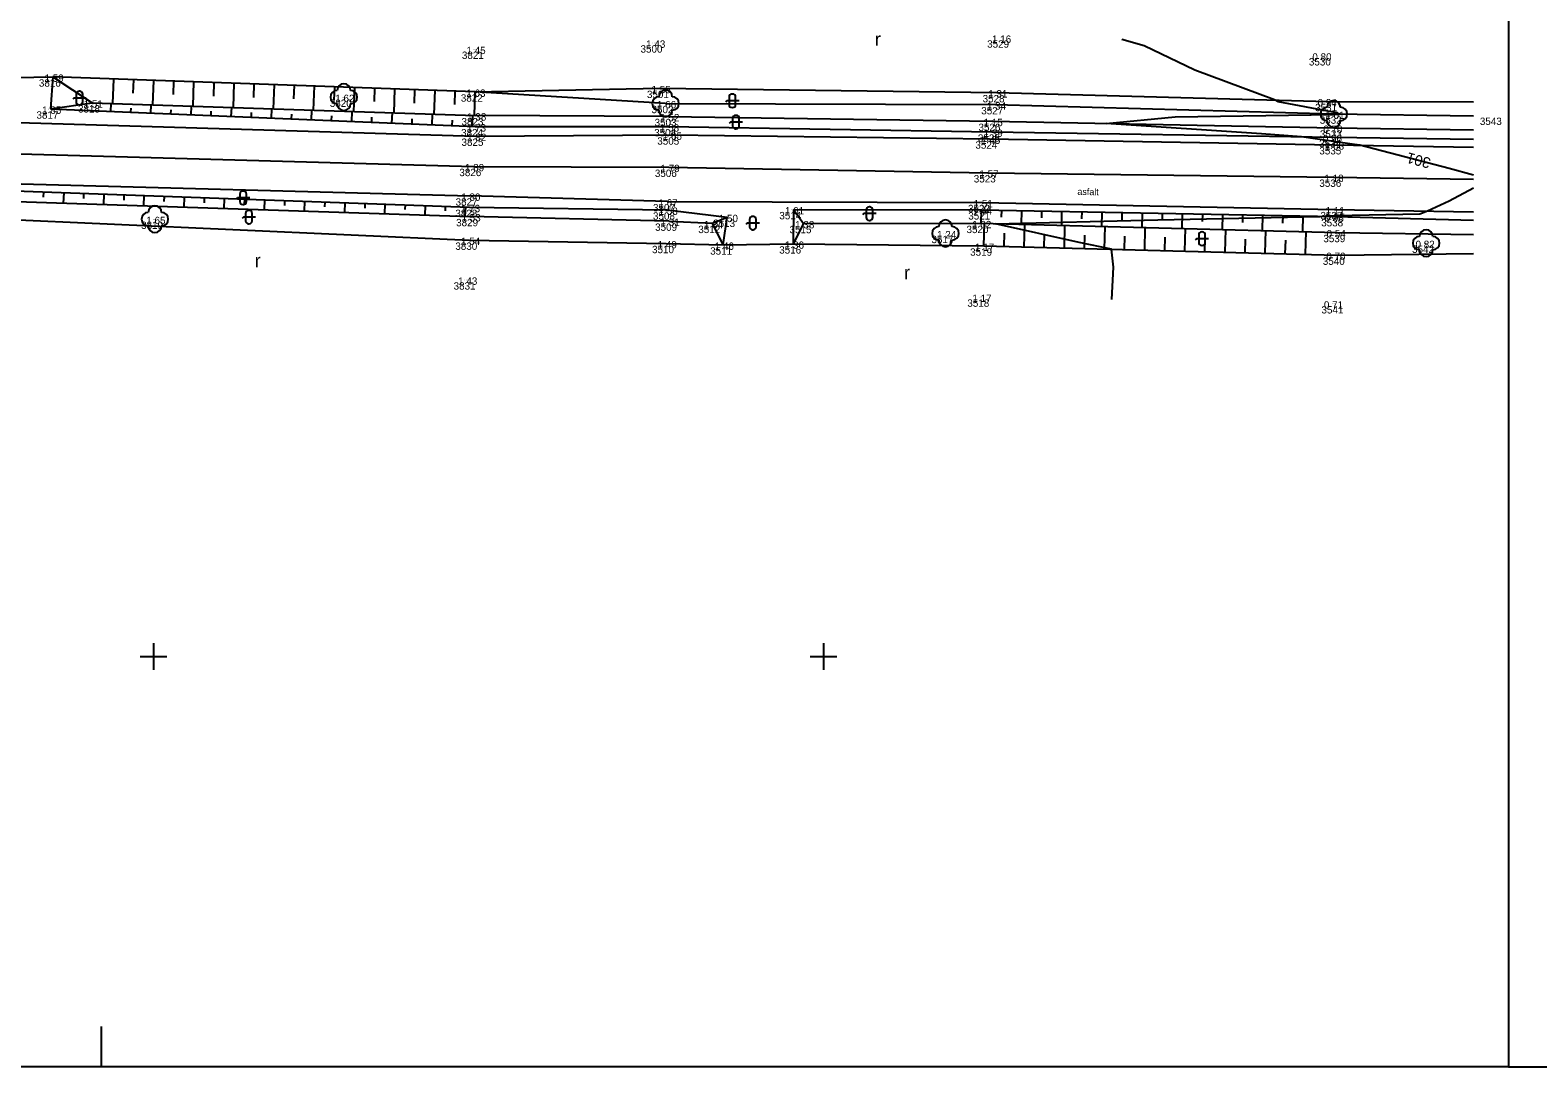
# Model space of a CAD drawing. Extents: x -740053 to -737517, y -1033516 to -1032476.
# Drawn here: x -739209.2 to -739096.7, y -1032630.6 to -1032553.3 of the extents above; entities that cross this region are included whole.
import ezdxf

# ---------------------------------------------------------------- set-up
doc = ezdxf.new("R2010")
doc.units = 0
for name, color, linetype in [('bod-cislo', 7, 'Continuous'), ('bod-oznac', 7, 'Continuous'), ('bod-vyska', 7, 'Continuous'), ('bod-vyska100', 7, 'Continuous'), ('Contours', 7, 'Continuous'), ('Contours text', 7, 'Continuous'), ('ctv-sit', 7, 'Continuous'), ('nazvy-bud-povr', 7, 'Continuous'), ('osa-komunikace', 7, 'Continuous'), ('Predmety bez rozlišeni', 7, 'Continuous'), ('promika-formát', 7, 'Continuous'), ('rozhraní kultůr', 7, 'Continuous'), ('silnice', 7, 'Continuous'), ('Technické šrafy', 7, 'Continuous'), ('Terenni-hrana', 7, 'Continuous'), ('Znacky-kultury', 7, 'Continuous')]:
    doc.layers.add(name, color=color, linetype=linetype)

# ---------------------------------------------------------------- blocks, each defined once
blk = doc.blocks.new('POINT_DISPLAY')
blk.add_line((0, 0), (0, 0))
blk = doc.blocks.new('p_strom')
for centre, start, end in [((-1, 0), 90, 270), ((0, 1), 0, 180), ((1, 0), 270, 90), ((0, -1), 180, 0)]:
    blk.add_arc(centre, 1, start, end)
at = {"rotation": -180}
blk.add_blockref('POINT_DISPLAY', (0, 0), dxfattribs=at)
blk = doc.blocks.new('p_neplod')
for p, q in [((-0.82, 0), (-0.99, -0.18)), ((1, 0), (-0.82, 0)), ((-0.49, 0.56), (-0.49, -0.55)), ((0.05, 1.01), (-0.04, 1.01)), ((0.5, -0.55), (0.5, 0.56)), ((-0.04, -1), (0.05, -1))]:
    blk.add_line(p, q)
for centre, start, end in [((-0.04, 0.56), 90, 180), ((0.05, 0.56), 0, 90), ((-0.04, -0.55), 180, 270), ((0.05, -0.55), 270, 0)]:
    blk.add_arc(centre, 0.45, start, end)
blk = doc.blocks.new('p_orna')
blk.add_text('r', height=2).set_placement((0, 0))
blk = doc.blocks.new('ctvsit')
for p, q in [((2, 0), (-2, 0)), ((0, -2), (0, 2))]:
    blk.add_line(p, q)

msp = doc.modelspace()

# ---------------------------------------------------------------- linework, layer by layer
at = {"layer": 'Contours'}
for points in [[(-739101.49, -1032564.07), (-739103.31, -1032563.58), (-739109.97, -1032561.84), (-739110.37, -1032561.79), (-739111.95, -1032561.56), (-739114.32, -1032561.21), (-739117.31, -1032561), (-739128.9, -1032560.22), (-739123.76, -1032559.73), (-739111.92, -1032559.54), (-739111.57, -1032559.53), (-739111.44, -1032559.52), (-739111.55, -1032559.51), (-739111.98, -1032559.38), (-739116.07, -1032558.61), (-739116.35, -1032558.46), (-739122.28, -1032556.24), (-739126.08, -1032554.42), (-739127.74, -1032553.96)], [(-739128.48, -1032573.35), (-739128.36, -1032570.95), (-739128.5, -1032569.61), (-739130.92, -1032569.09), (-739137.17, -1032567.7), (-739125.05, -1032567.42), (-739112.96, -1032567.15), (-739111.82, -1032567.09), (-739105.49, -1032566.96), (-739104.94, -1032566.75), (-739103.32, -1032565.98), (-739101.49, -1032565.01)]]:
    msp.add_lwpolyline(points, dxfattribs=at)
at = {"layer": 'osa-komunikace'}
for p, q in [((-739213.83, -1032562.39), (-739176.13, -1032563.42)), ((-739176.13, -1032563.42), (-739161.54, -1032563.48)), ((-739161.54, -1032563.48), (-739137.74, -1032563.89)), ((-739137.74, -1032563.89), (-739111.95, -1032564.22)), ((-739111.95, -1032564.22), (-739101.49, -1032564.37))]:
    msp.add_line(p, q, dxfattribs=at)
at = {"layer": 'Predmety bez rozlišeni'}
for p, q in [((-739203.88, -1032630.63), (-739203.88, -1032627.63)), ((-739203.88, -1032630.63), (-739308.88, -1032630.63)), ((-739098.88, -1032630.63), (-739203.88, -1032630.63))]:
    msp.add_line(p, q, dxfattribs=at)
at = {"layer": 'promika-formát'}
msp.add_lwpolyline([(-739098.88, -1032630.63), (-738993.88, -1032630.63), (-738993.88, -1032482.13), (-739098.88, -1032482.13)], close=True, dxfattribs=at)
at = {"layer": 'rozhraní kultůr'}
for p, q in [((-739213.24, -1032556.83), (-739207.51, -1032556.74)), ((-739176.02, -1032557.86), (-739162.21, -1032557.59)), ((-739162.21, -1032557.59), (-739137.08, -1032557.91)), ((-739137.08, -1032557.91), (-739112.34, -1032558.57)), ((-739112.34, -1032558.57), (-739101.49, -1032558.6)), ((-739214.13, -1032567.24), (-739176.43, -1032568.92)), ((-739176.43, -1032568.92), (-739161.75, -1032569.17)), ((-739161.75, -1032569.17), (-739157.49, -1032569.28))]:
    msp.add_line(p, q, dxfattribs=at)
at = {"layer": 'silnice'}
for p, q in [((-739213.3, -1032560.06), (-739175.97, -1032561.16)), ((-739175.97, -1032561.16), (-739161.36, -1032561.07)), ((-739161.36, -1032561.07), (-739137.61, -1032561.37)), ((-739137.61, -1032561.37), (-739111.95, -1032561.8)), ((-739111.95, -1032561.8), (-739101.49, -1032561.99)), ((-739213.9, -1032564.62), (-739176.41, -1032565.62)), ((-739161.68, -1032566.05), (-739176.41, -1032565.62)), ((-739161.68, -1032566.05), (-739138.17, -1032566.11)), ((-739138.17, -1032566.11), (-739111.87, -1032566.64)), ((-739111.87, -1032566.64), (-739101.49, -1032566.81))]:
    msp.add_line(p, q, dxfattribs=at)
at = {"layer": 'Technické šrafy'}
for p, q in [((-739203, -1032556.9), (-739203.07, -1032558.72)), ((-739201.5, -1032556.95), (-739201.54, -1032557.95)), ((-739200, -1032557.01), (-739200.07, -1032558.82)), ((-739198.51, -1032557.06), (-739198.54, -1032558.06)), ((-739197.01, -1032557.11), (-739197.07, -1032558.92)), ((-739195.51, -1032557.17), (-739195.54, -1032558.17)), ((-739194.01, -1032557.22), (-739194.07, -1032559.02)), ((-739192.51, -1032557.27), (-739192.55, -1032558.27)), ((-739191.01, -1032557.33), (-739191.07, -1032559.12)), ((-739189.51, -1032557.38), (-739189.55, -1032558.38)), ((-739188.01, -1032557.43), (-739188.08, -1032559.22)), ((-739186.51, -1032557.49), (-739186.55, -1032558.49)), ((-739185.01, -1032557.54), (-739185.08, -1032559.32)), ((-739183.52, -1032557.59), (-739183.55, -1032558.59)), ((-739182.02, -1032557.65), (-739182.08, -1032559.43)), ((-739180.52, -1032557.7), (-739180.55, -1032558.7)), ((-739179.02, -1032557.75), (-739179.08, -1032559.53)), ((-739177.52, -1032557.81), (-739177.55, -1032558.81)), ((-739176.02, -1032557.86), (-739176.08, -1032559.63)), ((-739203.19, -1032559.32), (-739203.17, -1032558.72)), ((-739201.7, -1032559.38), (-739201.68, -1032559.07)), ((-739200.2, -1032559.44), (-739200.17, -1032558.82)), ((-739197.2, -1032559.57), (-739197.17, -1032558.92)), ((-739194.2, -1032559.69), (-739194.17, -1032559.02)), ((-739198.7, -1032559.5), (-739198.68, -1032559.19)), ((-739195.7, -1032559.63), (-739195.69, -1032559.3)), ((-739192.7, -1032559.75), (-739192.69, -1032559.41)), ((-739191.2, -1032559.82), (-739191.18, -1032559.12)), ((-739189.71, -1032559.88), (-739189.69, -1032559.52)), ((-739188.21, -1032559.94), (-739188.18, -1032559.22)), ((-739186.71, -1032560), (-739186.69, -1032559.64)), ((-739185.21, -1032560.07), (-739185.18, -1032559.32)), ((-739183.71, -1032560.13), (-739183.7, -1032559.75)), ((-739182.21, -1032560.19), (-739182.18, -1032559.42)), ((-739180.71, -1032560.25), (-739180.7, -1032559.86)), ((-739179.21, -1032560.32), (-739179.18, -1032559.52)), ((-739177.72, -1032560.38), (-739177.7, -1032559.98)), ((-739176.22, -1032560.44), (-739176.18, -1032559.62)), ((-739208.21, -1032565.33), (-739208.23, -1032565.72)), ((-739206.71, -1032565.39), (-739206.74, -1032566.16)), ((-739205.22, -1032565.44), (-739205.23, -1032565.83)), ((-739203.72, -1032565.49), (-739203.74, -1032566.26)), ((-739202.22, -1032565.55), (-739202.23, -1032565.93)), ((-739200.72, -1032565.6), (-739200.75, -1032566.36)), ((-739199.22, -1032565.66), (-739199.23, -1032566.03)), ((-739197.72, -1032565.71), (-739197.75, -1032566.46)), ((-739196.22, -1032565.76), (-739196.23, -1032566.13)), ((-739194.72, -1032565.82), (-739194.75, -1032566.56)), ((-739193.22, -1032565.87), (-739193.24, -1032566.24)), ((-739191.72, -1032565.92), (-739191.75, -1032566.65)), ((-739190.23, -1032565.98), (-739190.24, -1032566.34)), ((-739188.73, -1032566.03), (-739188.75, -1032566.75)), ((-739187.23, -1032566.08), (-739187.24, -1032566.44)), ((-739185.73, -1032566.14), (-739185.75, -1032566.85)), ((-739184.23, -1032566.19), (-739184.24, -1032566.55)), ((-739182.73, -1032566.24), (-739182.76, -1032566.95)), ((-739181.23, -1032566.3), (-739181.24, -1032566.65)), ((-739179.73, -1032566.35), (-739179.76, -1032567.05)), ((-739178.23, -1032566.41), (-739178.25, -1032566.75)), ((-739176.73, -1032566.46), (-739176.76, -1032567.15)), ((-739138.23, -1032566.66), (-739138.25, -1032567.67)), ((-739136.73, -1032566.69), (-739136.74, -1032567.2)), ((-739135.23, -1032566.72), (-739135.25, -1032567.75)), ((-739133.73, -1032566.75), (-739133.74, -1032567.27)), ((-739132.23, -1032566.78), (-739132.25, -1032567.82)), ((-739130.73, -1032566.8), (-739130.74, -1032567.33)), ((-739129.23, -1032566.83), (-739129.25, -1032567.9)), ((-739127.73, -1032566.86), (-739127.74, -1032567.4)), ((-739126.23, -1032566.89), (-739126.25, -1032567.98)), ((-739124.73, -1032566.92), (-739124.74, -1032567.47)), ((-739123.23, -1032566.95), (-739123.25, -1032568.05)), ((-739138.03, -1032569.36), (-739137.99, -1032567.68)), ((-739135.03, -1032569.44), (-739134.99, -1032567.75)), ((-739132.03, -1032569.51), (-739131.99, -1032567.83)), ((-739129.03, -1032569.59), (-739128.99, -1032567.91)), ((-739126.03, -1032569.67), (-739125.99, -1032567.98)), ((-739123.03, -1032569.75), (-739122.99, -1032568.06)), ((-739121.73, -1032566.98), (-739121.74, -1032567.54)), ((-739120.23, -1032567.01), (-739120.26, -1032568.13)), ((-739118.73, -1032567.04), (-739118.74, -1032567.6)), ((-739117.23, -1032567.07), (-739117.26, -1032568.21)), ((-739115.73, -1032567.09), (-739115.75, -1032567.67)), ((-739114.23, -1032567.12), (-739114.26, -1032568.28)), ((-739136.53, -1032569.4), (-739136.5, -1032568.4)), ((-739133.53, -1032569.48), (-739133.51, -1032568.48)), ((-739130.53, -1032569.55), (-739130.51, -1032568.55)), ((-739127.53, -1032569.63), (-739127.51, -1032568.63)), ((-739124.53, -1032569.71), (-739124.51, -1032568.71)), ((-739121.54, -1032569.79), (-739121.51, -1032568.79)), ((-739120.04, -1032569.82), (-739119.99, -1032568.14)), ((-739118.54, -1032569.86), (-739118.51, -1032568.86)), ((-739117.04, -1032569.9), (-739116.99, -1032568.21)), ((-739115.54, -1032569.94), (-739115.51, -1032568.94)), ((-739114.04, -1032569.98), (-739113.99, -1032568.29))]:
    msp.add_line(p, q, dxfattribs=at)
at = {"layer": 'Terenni-hrana'}
for p, q in [((-739207.51, -1032556.74), (-739207.69, -1032559.13)), ((-739207.51, -1032556.74), (-739207.69, -1032559.13)), ((-739176.02, -1032557.86), (-739207.51, -1032556.74)), ((-739207.51, -1032556.74), (-739204.59, -1032558.67)), ((-739161.79, -1032558.72), (-739176.02, -1032557.86)), ((-739207.69, -1032559.13), (-739204.59, -1032558.67)), ((-739204.59, -1032558.67), (-739175.97, -1032559.63)), ((-739161.79, -1032558.72), (-739137.18, -1032558.81)), ((-739137.18, -1032558.81), (-739111.92, -1032559.51)), ((-739207.69, -1032559.13), (-739175.99, -1032560.45)), ((-739161.56, -1032559.69), (-739175.97, -1032559.63)), ((-739161.56, -1032559.69), (-739137.39, -1032560.05)), ((-739137.39, -1032560.05), (-739111.91, -1032560.55)), ((-739111.92, -1032559.51), (-739101.49, -1032559.65)), ((-739175.99, -1032560.45), (-739161.58, -1032560.45)), ((-739161.58, -1032560.45), (-739137.43, -1032560.85)), ((-739137.43, -1032560.85), (-739111.95, -1032561.25)), ((-739111.95, -1032561.25), (-739101.49, -1032561.39)), ((-739111.91, -1032560.55), (-739101.49, -1032560.7)), ((-739214.21, -1032565.12), (-739176.43, -1032566.47)), ((-739213.42, -1032565.94), (-739176.39, -1032567.16)), ((-739176.43, -1032566.47), (-739161.68, -1032566.67)), ((-739161.68, -1032566.67), (-739157.19, -1032567.21)), ((-739152.24, -1032566.64), (-739152.26, -1032569.2)), ((-739152.24, -1032566.64), (-739138.23, -1032566.66)), ((-739152.24, -1032566.64), (-739151.49, -1032567.68)), ((-739138.23, -1032566.66), (-739111.81, -1032567.17)), ((-739161.54, -1032567.5), (-739176.39, -1032567.16)), ((-739161.54, -1032567.5), (-739158.3, -1032567.67)), ((-739158.3, -1032567.67), (-739157.19, -1032567.21)), ((-739157.49, -1032569.28), (-739158.3, -1032567.67)), ((-739157.49, -1032569.28), (-739157.19, -1032567.21)), ((-739151.49, -1032567.68), (-739152.26, -1032569.2)), ((-739151.49, -1032567.68), (-739138.28, -1032567.67)), ((-739138.28, -1032567.67), (-739111.67, -1032568.35)), ((-739111.81, -1032567.17), (-739101.49, -1032567.43)), ((-739157.49, -1032569.28), (-739152.26, -1032569.2)), ((-739152.26, -1032569.2), (-739138.03, -1032569.36)), ((-739111.67, -1032568.35), (-739101.49, -1032568.5)), ((-739138.03, -1032569.36), (-739111.69, -1032570.04)), ((-739111.69, -1032570.04), (-739101.49, -1032569.93))]:
    msp.add_line(p, q, dxfattribs=at)

# ---------------------------------------------------------------- block references
at = {"layer": 'bod-oznac'}
for p in [(-739162.61, -1032554.2), (-739136.76, -1032553.83), (-739176.02, -1032554.67), (-739112.73, -1032555.16), (-739207.51, -1032556.74), (-739176.02, -1032557.86), (-739162.21, -1032557.59), (-739137.08, -1032557.91), (-739204.59, -1032558.67), (-739185.8, -1032558.25), (-739161.79, -1032558.72), (-739137.18, -1032558.81), (-739112.34, -1032558.57), (-739207.69, -1032559.13), (-739175.97, -1032559.63), (-739161.56, -1032559.69), (-739137.39, -1032560.05), (-739111.92, -1032559.51), (-739175.99, -1032560.45), (-739175.97, -1032561.16), (-739161.58, -1032560.45), (-739161.36, -1032561.07), (-739137.43, -1032560.85), (-739111.95, -1032561.25), (-739111.91, -1032560.55), (-739137.61, -1032561.37), (-739111.95, -1032561.8), (-739176.13, -1032563.42), (-739161.54, -1032563.48), (-739137.74, -1032563.89), (-739111.95, -1032564.22), (-739176.41, -1032565.62), (-739176.43, -1032566.47), (-739161.68, -1032566.05), (-739161.68, -1032566.67), (-739152.24, -1032566.64), (-739138.23, -1032566.66), (-739138.17, -1032566.11), (-739111.87, -1032566.64), (-739199.9, -1032567.36), (-739176.39, -1032567.16), (-739161.54, -1032567.5), (-739158.3, -1032567.67), (-739157.19, -1032567.21), (-739151.49, -1032567.68), (-739138.28, -1032567.67), (-739111.81, -1032567.17), (-739176.43, -1032568.92), (-739161.75, -1032569.17), (-739152.26, -1032569.2), (-739140.9, -1032568.42), (-739111.67, -1032568.35), (-739105.03, -1032569.15), (-739157.49, -1032569.28), (-739138.03, -1032569.36), (-739111.69, -1032570.04), (-739176.64, -1032571.89), (-739138.22, -1032573.17), (-739111.87, -1032573.67)]:
    msp.add_blockref('POINT_DISPLAY', p, dxfattribs=at)
at = {"layer": 'ctv-sit', "xscale": 0.5, "yscale": 0.5, "rotation": 180}
for p in [(-739200, -1032600), (-739150, -1032600)]:
    msp.add_blockref('ctvsit', p, dxfattribs=at)
at = {"layer": 'Znacky-kultury', "xscale": 0.5, "yscale": 0.5}
for name, p in [('p_orna', (-739146.17, -1032554.42)), ('p_neplod', (-739205.54, -1032558.32)), ('p_strom', (-739185.8, -1032558.25)), ('p_strom', (-739161.79, -1032558.72)), ('p_neplod', (-739156.81, -1032558.53)), ('p_strom', (-739111.92, -1032559.51)), ('p_neplod', (-739156.54, -1032560.12)), ('p_neplod', (-739193.32, -1032565.77)), ('p_strom', (-739199.9, -1032567.36)), ('p_neplod', (-739192.89, -1032567.21)), ('p_neplod', (-739146.58, -1032566.95)), ('p_neplod', (-739155.28, -1032567.66)), ('p_strom', (-739140.9, -1032568.42)), ('p_neplod', (-739121.76, -1032568.82)), ('p_strom', (-739105.03, -1032569.15)), ('p_orna', (-739192.45, -1032570.95)), ('p_orna', (-739143.99, -1032571.84))]:
    msp.add_blockref(name, p, dxfattribs=at)

# ---------------------------------------------------------------- texts
at = {"layer": 'bod-cislo'}
for s, p in [('3500', (-739163.66, -1032554.93)), ('3529', (-739137.79, -1032554.56)), ('3821', (-739176.99, -1032555.4)), ('3530', (-739113.78, -1032555.89)), ('3816', (-739208.56, -1032557.47)), ('3501', (-739163.18, -1032558.32)), ('3818', (-739205.64, -1032559.4)), ('3820', (-739186.85, -1032558.98)), ('3822', (-739177.07, -1032558.59)), ('3502', (-739162.84, -1032559.45)), ('3527', (-739138.23, -1032559.54)), ('3528', (-739138.13, -1032558.64)), ('3531', (-739113.31, -1032559.3)), ('3817', (-739208.74, -1032559.86)), ('3823', (-739177.02, -1032560.36)), ('3503', (-739162.61, -1032560.42)), ('3532', (-739112.97, -1032560.24)), ('3543', (-739101.02, -1032560.33)), ('3824', (-739177.05, -1032561.18)), ('3825', (-739177.02, -1032561.89)), ('3504', (-739162.64, -1032561.18)), ('3505', (-739162.41, -1032561.8)), ('3525', (-739138.48, -1032561.58)), ('3526', (-739138.44, -1032560.78)), ('3533', (-739112.96, -1032561.28)), ('3524', (-739138.67, -1032562.1)), ('3534', (-739113.01, -1032561.98)), ('3535', (-739113, -1032562.53)), ('3826', (-739177.18, -1032564.15)), ('3506', (-739162.59, -1032564.21)), ('3523', (-739138.79, -1032564.62)), ('3536', (-739113, -1032564.95)), ('3827', (-739177.46, -1032566.35)), ('3828', (-739177.48, -1032567.2)), ('3507', (-739162.73, -1032566.78)), ('3508', (-739162.73, -1032567.4)), ('3514', (-739153.3, -1032567.37)), ('3522', (-739139.22, -1032566.84)), ('3521', (-739139.2, -1032567.39)), ('3537', (-739112.92, -1032567.37)), ('3819', (-739200.93, -1032568.09)), ('3829', (-739177.42, -1032567.89)), ('3509', (-739162.57, -1032568.23)), ('3512', (-739159.35, -1032568.4)), ('3513', (-739158.24, -1032567.94)), ('3515', (-739152.54, -1032568.41)), ('3520', (-739139.33, -1032568.4)), ('3538', (-739112.86, -1032567.9)), ('3830', (-739177.48, -1032569.65)), ('3517', (-739141.95, -1032569.15)), ('3539', (-739112.7, -1032569.08)), ('3510', (-739162.8, -1032569.9)), ('3511', (-739158.46, -1032570.01)), ('3516', (-739153.31, -1032569.93)), ('3519', (-739139.06, -1032570.09)), ('3540', (-739112.74, -1032570.77)), ('3542', (-739106.08, -1032569.88)), ('3831', (-739177.61, -1032572.62)), ('3518', (-739139.27, -1032573.9)), ('3541', (-739112.84, -1032574.4))]:
    msp.add_text(s, height=0.55, dxfattribs=at).set_placement(p)
at = {"layer": 'bod-vyska'}
for s, p in [('1 45', (-739176.65, -1032555.04)), ('1 43', (-739163.24, -1032554.57)), ('1 16', (-739137.43, -1032554.2)), ('0 80', (-739113.52, -1032555.53)), ('1 59', (-739208.14, -1032557.11)), ('1 63', (-739176.66, -1032558.23)), ('1 55', (-739162.84, -1032557.96)), ('1 31', (-739137.71, -1032558.28)), ('1 85', (-739208.32, -1032559.5)), ('1 51', (-739205.22, -1032559.04)), ('1 62', (-739186.44, -1032558.62)), ('1 66', (-739162.43, -1032559.09)), ('1 34', (-739137.81, -1032559.18)), ('0 94', (-739113.13, -1032558.94)), ('1 38', (-739176.6, -1032560)), ('1 52', (-739162.19, -1032560.06)), ('1 15', (-739138.06, -1032560.42)), ('1 01', (-739112.55, -1032559.88)), ('1 73', (-739176.62, -1032560.82)), ('1 82', (-739176.6, -1032561.53)), ('1 58', (-739162.21, -1032560.82)), ('1 65', (-739162, -1032561.44)), ('1 45', (-739138.24, -1032561.74)), ('1 39', (-739138.06, -1032561.22)), ('0 96', (-739112.74, -1032561.62)), ('0 70', (-739112.7, -1032560.92)), ('1 03', (-739112.58, -1032562.17)), ('1 89', (-739176.76, -1032563.79)), ('1 79', (-739162.17, -1032563.85)), ('1 57', (-739138.37, -1032564.26)), ('1 18', (-739112.62, -1032564.59)), ('1 80', (-739177.04, -1032565.99)), ('1 73', (-739177.06, -1032566.84)), ('1 67', (-739162.32, -1032566.42)), ('1 58', (-739162.31, -1032567.04)), ('1 61', (-739152.88, -1032567.01)), ('1 44', (-739138.86, -1032567.03)), ('1 51', (-739138.8, -1032566.48)), ('1 11', (-739112.54, -1032567.01)), ('1 65', (-739200.54, -1032567.73)), ('1 53', (-739177.02, -1032567.53)), ('1 31', (-739162.17, -1032567.87)), ('1 34', (-739158.93, -1032568.04)), ('1 50', (-739157.82, -1032567.58)), ('1 38', (-739152.12, -1032568.05)), ('1 02', (-739138.91, -1032568.04)), ('0 98', (-739112.6, -1032567.54)), ('1 54', (-739177.06, -1032569.29)), ('1 49', (-739162.38, -1032569.54)), ('1 46', (-739158.12, -1032569.65)), ('1 36', (-739152.89, -1032569.57)), ('1 24', (-739141.53, -1032568.79)), ('1 17', (-739138.7, -1032569.73)), ('0 54', (-739112.46, -1032568.72)), ('0 82', (-739105.82, -1032569.52)), ('0 70', (-739112.48, -1032570.41)), ('1 43', (-739177.27, -1032572.26)), ('1 17', (-739138.89, -1032573.54)), ('0 71', (-739112.66, -1032574.04))]:
    msp.add_text(s, height=0.55, dxfattribs=at).set_placement(p)
at = {"layer": 'bod-vyska100'}
for s, p in [('301 43', (-739162.77, -1032554.23)), ('301 16', (-739136.92, -1032553.86)), ('301 45', (-739176.18, -1032554.7)), ('300 80', (-739112.9, -1032555.19)), ('301 59', (-739207.67, -1032556.77)), ('301 63', (-739176.18, -1032557.89)), ('301 55', (-739162.37, -1032557.62)), ('301 31', (-739137.24, -1032557.94)), ('301 51', (-739204.75, -1032558.7)), ('301 62', (-739185.96, -1032558.28)), ('301 66', (-739161.95, -1032558.75)), ('301 34', (-739137.34, -1032558.84)), ('300 94', (-739112.51, -1032558.6)), ('301 85', (-739207.85, -1032559.16)), ('301 38', (-739176.13, -1032559.66)), ('301 52', (-739161.72, -1032559.72)), ('301 15', (-739137.55, -1032560.08)), ('301 01', (-739112.08, -1032559.54)), ('301 73', (-739176.15, -1032560.48)), ('301 82', (-739176.13, -1032561.19)), ('301 58', (-739161.74, -1032560.48)), ('301 65', (-739161.52, -1032561.1)), ('301 39', (-739137.59, -1032560.88)), ('300 96', (-739112.12, -1032561.28)), ('300 70', (-739112.08, -1032560.58)), ('301 45', (-739137.77, -1032561.4)), ('301 03', (-739112.11, -1032561.83)), ('301 89', (-739176.29, -1032563.45)), ('301 79', (-739161.7, -1032563.51)), ('301 57', (-739137.9, -1032563.92)), ('301 18', (-739112.11, -1032564.25)), ('301 80', (-739176.57, -1032565.65)), ('301 73', (-739176.59, -1032566.5)), ('301 67', (-739161.84, -1032566.08)), ('301 58', (-739161.84, -1032566.7)), ('301 61', (-739152.4, -1032566.67)), ('301 44', (-739138.39, -1032566.69)), ('301 51', (-739138.33, -1032566.14)), ('301 11', (-739112.03, -1032566.67)), ('301 65', (-739200.06, -1032567.39)), ('301 53', (-739176.55, -1032567.19)), ('301 31', (-739161.7, -1032567.53)), ('301 34', (-739158.46, -1032567.7)), ('301 50', (-739157.35, -1032567.24)), ('301 38', (-739151.65, -1032567.71)), ('301 02', (-739138.44, -1032567.7)), ('300 98', (-739111.98, -1032567.2)), ('301 54', (-739176.59, -1032568.95)), ('301 49', (-739161.91, -1032569.2)), ('301 36', (-739152.42, -1032569.23)), ('301 24', (-739141.06, -1032568.45)), ('300 54', (-739111.84, -1032568.38)), ('300 82', (-739105.2, -1032569.18)), ('301 46', (-739157.65, -1032569.31)), ('301 17', (-739138.19, -1032569.39)), ('300 70', (-739111.86, -1032570.07)), ('301 43', (-739176.8, -1032571.92)), ('301 17', (-739138.38, -1032573.2)), ('300 71', (-739112.04, -1032573.7))]:
    msp.add_text(s, height=0.05, dxfattribs=at).set_placement(p)
at = {"layer": 'Contours text'}
msp.add_text('301', height=0.8, rotation=165.2999, dxfattribs=at).set_placement((-739104.63, -1032562.82))
at = {"layer": 'nazvy-bud-povr'}
msp.add_text('asfalt', height=0.5, rotation=358.9031, dxfattribs=at).set_placement((-739131.06, -1032565.55))

doc.saveas('drawing.dxf')
